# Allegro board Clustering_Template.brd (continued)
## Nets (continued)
TRST_N: J1.R3 U1.AJ16 U2.AJ16 U3.AJ16 U4.AJ16
VMON_RST: Q1.1 U5.1
$2N1105: C118.2(N2) R126.1
$2N1108: C119.2(N2) R127.1
$3N1161: C686.2(N2) R82.1
$3N1168: C687.2(N2) R83.1
$4N1261: C688.2(N2) R84.1
$4N1262: C689.2(N2) R85.1
$5N1498: C690.2(N2) R139.1
$5N1499: C691.2(N2) R142.1

Pads without a net: J2 1 2 3 36 37 38; J3 1 2 3 28 36 37 38; J4 1 2 3 36 37 38; J5 1 2 6 33 36 37 38; J6 1 2 36 37 38; PS1 2; RA1 3 4 5 6; RA22 3 4 5 6; RA26 3 4 5 6; RA30 3 4 5 6; RA33 3 4 5 6; U1 A24 AF2 AF3 AG1 AG2 AG3 AH2 AH3 AJ4 AJ5 AJ6 AJ7 AJ8 AJ9 AJ10 AJ11 AJ12 AJ13 AJ14 AJ17 AJ18 AJ19 AJ21 AJ22 AJ26 AK4 AK5 AK6 AK7 AK8 AK9 AK10 AK11 AK12 AK13 AK14 AK17 AK18 AK19 AK22 AK23 AL5 AL6 AL7 AL8 AL9 AL10 AL11 AL12 AL13 AL18 AL19 AL22 AL23 B21 B24 C21 C23 D2 D3 E2 E3 F1 F2 F3 G1 G2 G3 H1 H2 H3 J3 P1 P30 T1 T31 U1 U2 U3 V1 W31; U2 A24 AF2 AF3 AG1 AG2 AG3 AH2 AH3 AJ4 AJ5 AJ6 AJ7 AJ8 AJ9 AJ10 AJ11 AJ12 AJ13 AJ14 AJ17 AJ18 AJ19 AJ21 AJ22 AJ26 AK4 AK5 AK6 AK7 AK8 AK9 AK10 AK11 AK12 AK13 AK14 AK17 AK18 AK19 AK22 AK23 AL5 AL6 AL7 AL8 AL9 AL10 AL11 AL12 AL13 AL18 AL19 AL22 AL23 B21 B24 C21 C23 D2 D3 E2 E3 F1 F2 F3 G1 G2 G3 H1 H2 H3 J3 P1 P30 T1 T31 U1 U2 U3 V1 W31; U3 A24 AF2 AF3 AG1 AG2 AG3 AH2 AH3 AJ4 AJ5 AJ6 AJ7 AJ8 AJ9 AJ10 AJ11 AJ12 AJ13 AJ14 AJ17 AJ18 AJ19 AJ21 AJ22 AJ26 AK4 AK5 AK6 AK7 AK8 AK9 AK10 AK11 AK12 AK13 AK14 AK17 AK18 AK19 AK22 AK23 AL5 AL6 AL7 AL8 AL9 AL10 AL11 AL12 AL13 AL18 AL19 AL22 AL23 B21 B24 C21 C23 D2 D3 E2 E3 F1 F2 F3 G1 G2 G3 H1 H2 H3 J3 P1 P30 T1 T31 U1 U2 U3 V1 W31; U4 A24 AF2 AF3 AG1 AG2 AG3 AH2 AH3 AJ4 AJ5 AJ6 AJ7 AJ8 AJ9 AJ10 AJ11 AJ12 AJ13 AJ14 AJ17 AJ18 AJ19 AJ21 AJ22 AJ26 AK4 AK5 AK6 AK7 AK8 AK9 AK10 AK11 AK12 AK13 AK14 AK17 AK18 AK19 AK22 AK23 AL5 AL6 AL7 AL8 AL9 AL10 AL11 AL12 AL13 AL18 AL19 AL22 AL23 B21 B24 C21 C23 D2 D3 E2 E3 F1 F2 F3 G1 G2 G3 H1 H2 H3 J3 P1 P30 T1 T31 U1 U2 U3 V1 W31
